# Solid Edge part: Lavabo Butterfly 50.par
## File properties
Title: LAVABO BUTTERFLY 50 APP. O SOSP.
Author: DESYS
Template: Iso Part.par
Last saved by: PIM_1
Revision: 90
Application: Solid Edge
Tipo di contenuto documento: 0
Accuracy: 0,990
Document Number: 4003
Revision: 0
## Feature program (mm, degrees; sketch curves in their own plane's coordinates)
sketch for "unnamed Protrusion 1" plane through (10.8674, 0, 10.8674) normal (0, -1, 0) x-axis (1, 0, 0)
  line (-263.3674, 134.1326) -> (241.6326, 134.1326)
  line (241.6326, 134.1326) -> (241.6326, 94.1326)
  arc centre (268.5771, -79.796) radius 176.0033 from (241.6326, 94.1326) to (106.6326, -10.8674) ccw
  line (106.6326, -10.8674) -> (-128.3674, -10.8674)
  arc centre (-290.3118, -79.796) radius 176.0033 from (-128.3674, -10.8674) to (-263.3674, 94.1326) ccw
  line (-263.3674, 94.1326) -> (-263.3674, 134.1326)
  dimension (linear) = 263.3674
  dimension (linear) = 241.6326
  dimension (linear) = 106.6326
  dimension (linear) = 106.6326
extrude "unnamed Protrusion 1" add finite 460 along -normal
sketch for "ScavoEstrusione_1" plane through (-252.5, 230, 130) normal (-1, 0, 0) x-axis (0, 1, 0)
  arc centre (311.0161, 311.5) radius 297.7346 from (230, 25) to (75, 130) cw
extrude "ScavoEstrusione_1" cut finite 1680 symmetric
sketch for "ScavoEstrusione_3" plane through (0, 152.5, 0) normal (0, 0, -1) x-axis (-1, 0, 0)
extrude "ScavoEstrusione_3" cut finite 143 along -normal
sketch for "ScavoEstrusione_4" plane through (0, 152.5, 0) normal (0, 0, -1) x-axis (-1, 0, 0)
  line (-57.5, 117.5) -> (57.5, 117.5)
  arc centre (57.5, 97.5) radius 20 from (57.5, 117.5) to (77.5, 97.5) cw
  line (77.5, -22.5) -> (77.5, 97.5)
  line (-77.5, -22.5) -> (77.5, -22.5)
  line (-77.5, -22.5) -> (-77.5, 97.5)
  arc centre (-57.5, 97.5) radius 20 from (-57.5, 117.5) to (-77.5, 97.5) ccw
extrude "ScavoEstrusione_4" cut finite 25 along -normal
draft "Spoglia_4"  Angles1 = 5 deg
sketch for "ScavoEstrusione_6" plane through (0, 0, 75) normal (0, -1, 0) x-axis (-1, 0, 0)
extrude "ScavoEstrusione_6" cut finite 35 along -normal
fillet "Rotondo_3" radius 30
sketch for "ScavoEstrusione_11" #1 plane through (0, 0, 75) normal (0, -1, 0) x-axis (-1, 0, 0)
  circle centre (-222.5, -45) radius 7.5
sketch for "ScavoEstrusione_11" #2 plane through (0, 0, 75) normal (0, -1, 0) x-axis (-1, 0, 0)
  circle centre (222.5, -45) radius 7.5
extrude "ScavoEstrusione_11" cut finite 385 along -normal
sketch for "ScavoEstrusione_12" #1 plane through (0, 0, 75) normal (0, -1, 0) x-axis (-1, 0, 0)
  line (62.5, -30) -> (52.5, -30)
  arc centre (52.5, -20) radius 10 from (52.5, -30) to (52.5, -10) cw
  line (52.5, -10) -> (62.5, -10)
  arc centre (62.5, -20) radius 10 from (62.5, -10) to (62.5, -30) cw
sketch for "ScavoEstrusione_12" #2 plane through (0, 0, 75) normal (0, -1, 0) x-axis (-1, 0, 0)
  arc centre (-52.5, -20) radius 10 from (-52.5, -30) to (-52.5001, -10) ccw
  line (-52.5001, -10) -> (-62.4999, -10)
  arc centre (-62.5, -20) radius 10 from (-62.4999, -10) to (-62.5, -30) ccw
  line (-62.5, -30) -> (-52.5, -30)
extrude "ScavoEstrusione_12" cut finite 70 along -normal
sketch for "ProtrusioneEstrusa_2" plane through (0, 192.5, 25) normal (0, 0, -1) x-axis (-1, 0, 0)
extrude "ProtrusioneEstrusa_2" add finite 35 along +normal
sketch for "ScavoEstrusione_15" plane through (0, 230, 145) normal (0, 0, 1) x-axis (1, 0, 0)
extrude "ScavoEstrusione_15" cut finite 700 along -normal
lofted cutout "unnamed LoftedCutout 1"
sketch for "ScavoEstrusione_17" plane through (0, 136.8454, 94.8007) normal (0, 0.99083, 0.135113) x-axis (-1, 0, 0)
extrude "ScavoEstrusione_17" cut finite 35 along -normal
replace surface "unnamed ReplaceSurface 1"
sketch for "ProtrusioneEstrusa_6" plane through (0, 230, 130) normal (-1, 0, 0) x-axis (0, 1, 0)
  line (-56.6511, 130) -> (-135.3237, 130)
  line (-135.3237, -13) -> (-135.3237, 130)
  line (-135.3237, -13) -> (-110.3237, -13)
  line (-110.3237, -13) -> (-75, 105)
  line (-75, 105) -> (-59.3301, 105)
  dimension (linear) = 135.3237
extrude "ProtrusioneEstrusa_6" add finite 45 symmetric
fillet "Rotondo_7" radius 40
fillet "Rotondo_8" radius 5
fillet "Rotondo_13" radius 5
fillet "Rotondo_14" radius 5
fillet "Rotondo_15" radius 10
fillet "Rotondo_17" radius 9
fillet "Rotondo_21" radius 5
fillet "Rotondo_23" radius 2
fillet "Rotondo_25" radius 1
fillet "Rotondo_29" radius 5
replace surface "unnamed ReplaceSurface 2"
sketch for "ScavoEstrusione_18" plane through (0, 200, -10) normal (0, 0, -1) x-axis (-1, 0, 0)
  circle centre (0, 0) radius 22.5
extrude "ScavoEstrusione_18" cut finite 210 along -normal
sketch for "ScavoEstrusione_19" #1 plane through (0, 153.6655, 0) normal (0, 0, -1) x-axis (-1, 0, 0)
  circle centre (-96.2911, 128.8345) radius 7.5
sketch for "ScavoEstrusione_19" #2 plane through (0, 153.6655, 0) normal (0, 0, -1) x-axis (-1, 0, 0)
sketch for "ScavoEstrusione_19" #3 plane through (0, 153.6655, 0) normal (0, 0, -1) x-axis (-1, 0, 0)
  circle centre (96.2911, 128.8345) radius 7.5
sketch for "ScavoEstrusione_19" #4 plane through (0, 153.6655, 0) normal (0, 0, -1) x-axis (-1, 0, 0)
  circle centre (-106.7911, -141.6655) radius 5
extrude "ScavoEstrusione_19" cut finite 50 along -normal
fillet "Rotondo_34" radius 45
fillet "Rotondo_35" radius 5
fillet "Rotondo_36" radius 5
fillet "Rotondo_37" radius 2
fillet "Rotondo_38" radius 5
fillet "Rotondo_39" radius 5
fillet "Rotondo_41" radius 2
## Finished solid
Body 1: sheet body, 1 face, 4 edges, 4 vertices.
  Faces by surface: spline 1
  Edges by curve: intersection 2, circle 1, line 1
Body 2: solid body, 229 faces, 483 edges, 254 vertices.
  Faces by surface: cylinder 89, torus 47, plane 37, blend 31, sphere 22, spline 2, swept 1
  Edges by curve: circle 255, line 162, intersection 57, ellipse 9
Bounding box of the edges (mm; curved faces can reach further): 505.000 x 460.000 x 155.000, from (-252.5, 0, -10) to (252.5, 460, 145).
Cylindrical faces by radius (mm): R2 x8, R5 x50, R7.5 x4, R9 x8, R10 x8, R20 x2, R22.5 x1, R30 x3, R40 x2, R45 x1, R176.0033 x2
Toroidal faces (ring radius, tube radius in mm): R5 r5 x4, R7 r2 x2, R9.5 r2 x4, R10 r5 x4, R12 r2 x8, R15 r5 x4, R21.5 r5 x1, R25 r5 x6, R27.5 r5 x1, R29 r1 x1, R35 r5 x2, R40 r5 x2, R45 r5 x4, R181.0033 r5 x2, R186.0033 r10 x2
Spherical faces by radius (mm): R5 x18, R9 x4
Planar faces by outward normal: +x 4, +y 2, +z 4, -x 4, -y 5, -z 11, oblique 7
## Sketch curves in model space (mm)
line (212.5, 130, 145) -> (-212.5, 130, 145)
line (-212.5, 130, 145) -> (-212.5, 430, 145)
arc centre (0, 2682.8125, 145) radius 2262.8125 from (212.5, 430, 145) through (0, 420, 145) to (-212.5, 430, 145)
line (212.5, 430, 145) -> (212.5, 130, 145)
line (72.5, 145, 35) -> (-27.5, 145, 35)
line (-27.5, 145, 35) -> (-27.5, 265, 35)
line (-27.5, 265, 35) -> (72.5, 265, 35)
line (72.5, 265, 35) -> (72.5, 145, 35)
arc centre (0, 460, -6268.125) radius 6378.125 from (252.5, 460, 105) through (0, 460, 110) to (-252.5, 460, 105)
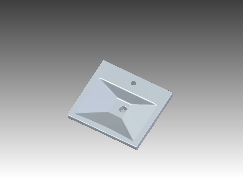
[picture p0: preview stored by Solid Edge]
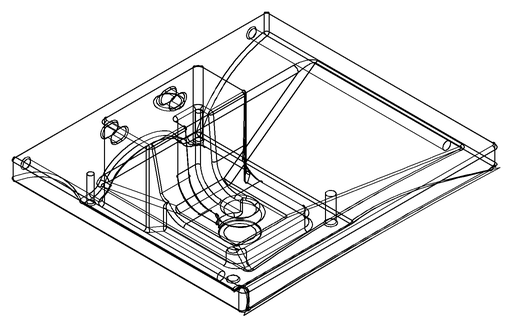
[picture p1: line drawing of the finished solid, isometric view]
